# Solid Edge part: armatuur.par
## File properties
Author: Georg
Template: Iso Part.par
Last saved by: Kalle
Revision: 8
Application: Solid Edge
Accuracy: 0,990
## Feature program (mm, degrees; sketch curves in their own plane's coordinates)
sketch for "unnamed Protrusion 1" plane through (0, 0, 0) normal (0, 0, 1) x-axis (1, 0, 0)
  line (24.0787, 14.5112) -> (30.0787, 14.5112)
  line (30.0787, 14.5112) -> (30.0787, 41.5112)
  line (30.0787, 41.5112) -> (24.0787, 41.5112)
  line (24.0787, 41.5112) -> (24.0787, 14.5112)
  dimension (linear) = 30.0787
  dimension (linear) = 30.0787
extrude "unnamed Protrusion 1" add finite 9 along +normal
sketch for "ExtrudedCutout_1" plane through (24.0787, 28.0112, 4.5) normal (-1, 0, 0) x-axis (0, -1, 0)
  circle centre (0, 0) radius 1
extrude "ExtrudedCutout_1" cut finite 1 along -normal
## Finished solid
Body 1: solid body, 8 faces, 14 edges, 8 vertices.
  Faces by surface: plane 7, cylinder 1
  Edges by curve: line 12, circle 2
Bounding box of the edges (mm): 6.000 x 27.000 x 9.000, from (24.0787, 14.5112, 0) to (30.0787, 41.5112, 9).
Cylindrical faces by radius (mm): R1 x1
Planar faces by outward normal: +x 1, +y 1, +z 1, -x 2, -y 1, -z 1
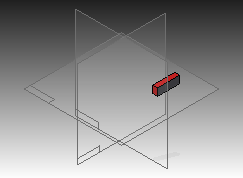
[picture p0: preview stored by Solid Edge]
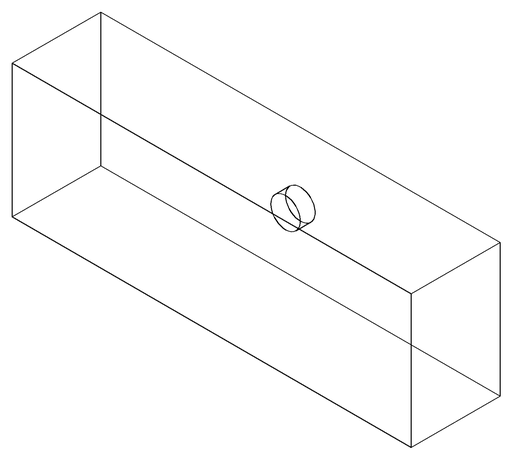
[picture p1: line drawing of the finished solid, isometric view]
